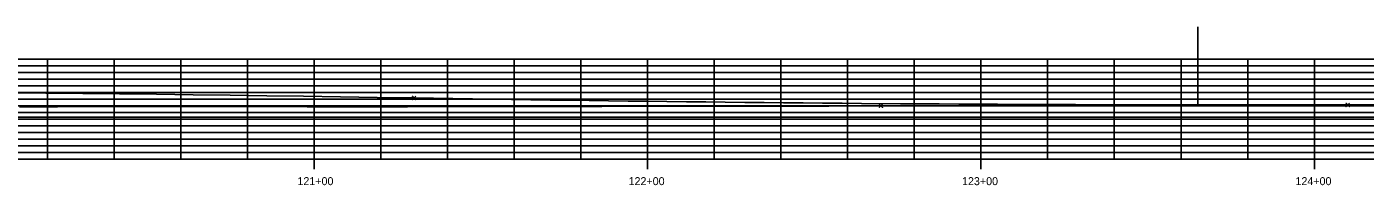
# Model space of a CAD drawing. Extents: x 1676565 to 1681112, y 227357 to 229815.
# Drawn here: x 1680181.1 to 1680582.6, y 229581 to 229628.6 of the extents above; entities that cross this region are included whole.
import ezdxf

# ---------------------------------------------------------------- set-up
doc = ezdxf.new("R2010")
doc.units = 0
for name, color, linetype in [('Default', 7, 'Continuous'), ('R_Axis', 7, 'Continuous'), ('R_Axis Annot', 7, 'Continuous'), ('R_Exist Surface', 7, 'Continuous'), ('R_Grid', 7, 'Continuous'), ('R_No Plot', 7, 'Continuous'), ('R_Point Sym', 7, 'Continuous'), ('R_Water', 7, 'Continuous')]:
    doc.layers.add(name, color=color, linetype=linetype)

msp = doc.modelspace()

# ---------------------------------------------------------------- linework, layer by layer
at = {"layer": 'Default'}
for points in [[(1680175.85, 229608.79), (1680186.89, 229608.68), (1680197.93, 229608.56), (1680208.97, 229608.44), (1680220.02, 229608.31), (1680231.06, 229608.17), (1680242.1, 229608.03), (1680253.14, 229607.88), (1680264.18, 229607.72), (1680275.22, 229607.56), (1680286.27, 229607.39), (1680297.31, 229607.21)], [(1680297.31, 229607.21), (1680303.14, 229607.11), (1680308.97, 229607.02), (1680314.81, 229606.93), (1680320.64, 229606.84), (1680326.47, 229606.75), (1680332.31, 229606.67), (1680338.14, 229606.59), (1680343.97, 229606.51), (1680349.81, 229606.43), (1680355.64, 229606.36), (1680361.47, 229606.28), (1680367.31, 229606.21), (1680373.14, 229606.14), (1680378.97, 229606.08), (1680384.81, 229606.01), (1680390.64, 229605.95), (1680396.47, 229605.89), (1680402.31, 229605.83), (1680408.14, 229605.78), (1680413.97, 229605.73), (1680419.81, 229605.68), (1680425.64, 229605.63), (1680431.47, 229605.58), (1680443.14, 229605.5), (1680448.97, 229605.46), (1680454.81, 229605.42), (1680460.64, 229605.38), (1680466.47, 229605.35), (1680472.31, 229605.32), (1680478.14, 229605.29), (1680483.97, 229605.27), (1680489.81, 229605.24), (1680495.64, 229605.22), (1680501.47, 229605.2), (1680507.31, 229605.18), (1680513.14, 229605.17), (1680518.97, 229605.15), (1680524.81, 229605.14), (1680530.64, 229605.14), (1680536.47, 229605.13), (1680542.31, 229605.13), (1680548.14, 229605.12), (1680553.97, 229605.12), (1680559.81, 229605.13), (1680565.64, 229605.13), (1680571.47, 229605.14), (1680577.31, 229605.15)]]:
    msp.add_lwpolyline(points, dxfattribs=at)
at = {"layer": 'R_Axis'}
msp.add_line((1678167.31, 229588.83), (1681067.31, 229588.83), dxfattribs=at)
at = {"layer": 'R_Exist Surface'}
msp.add_lwpolyline([(1680178.98, 229604.58), (1680190.32, 229604.59), (1680203.93, 229604.61), (1680204.12, 229604.61), (1680204.84, 229604.61), (1680227.46, 229604.63), (1680228.89, 229604.63), (1680229.3, 229604.63), (1680250.08, 229604.61), (1680250.24, 229604.61), (1680265.2, 229604.6), (1680271.59, 229604.59), (1680272.71, 229604.59), (1680277.09, 229604.59), (1680290.61, 229604.6), (1680290.79, 229604.6), (1680290.97, 229604.6), (1680295.33, 229604.6), (1680309.99, 229604.61), (1680310.28, 229604.61), (1680317.96, 229604.63), (1680324.46, 229604.64), (1680324.72, 229604.64), (1680338.94, 229604.67), (1680339.15, 229604.67), (1680353.42, 229604.7), (1680353.59, 229604.7), (1680367.9, 229604.72), (1680368.01, 229604.72), (1680381.34, 229604.73), (1680381.42, 229604.74), (1680394.79, 229604.75), (1680394.83, 229604.75), (1680408.23, 229604.76), (1680408.24, 229604.76), (1680413.34, 229604.76), (1680421.65, 229604.77), (1680421.67, 229604.77), (1680434.92, 229604.81), (1680434.93, 229604.81), (1680448.18, 229604.86), (1680461.43, 229604.91), (1680474.67, 229604.95), (1680474.69, 229604.95), (1680474.72, 229604.95), (1680495.86, 229604.97), (1680496.13, 229604.97), (1680511.62, 229605.01), (1680511.74, 229605.01), (1680525.33, 229605.04), (1680527.35, 229605.05), (1680527.37, 229605.05), (1680540.79, 229605.08), (1680540.88, 229605.08), (1680554.22, 229605.1), (1680554.38, 229605.1), (1680554.54, 229605.1), (1680567.88, 229605.13), (1680568.11, 229605.13), (1680581.37, 229605.16), (1680581.73, 229605.16), (1680596.3, 229605.16)], dxfattribs=at)
at = {"layer": 'R_Grid'}
for p, q in [((1678167.31, 229618.83), (1681067.31, 229618.83)), ((1678167.31, 229618.83), (1681067.31, 229618.83)), ((1678167.31, 229616.83), (1681067.31, 229616.83)), ((1680187.31, 229588.83), (1680187.31, 229618.83)), ((1680207.31, 229588.83), (1680207.31, 229618.83)), ((1680227.31, 229588.83), (1680227.31, 229618.83)), ((1680247.31, 229588.83), (1680247.31, 229618.83)), ((1680267.31, 229588.83), (1680267.31, 229618.83)), ((1680287.31, 229588.83), (1680287.31, 229618.83)), ((1680307.31, 229588.83), (1680307.31, 229618.83)), ((1680327.31, 229588.83), (1680327.31, 229618.83)), ((1680347.31, 229588.83), (1680347.31, 229618.83)), ((1680367.31, 229588.83), (1680367.31, 229618.83)), ((1680387.31, 229588.83), (1680387.31, 229618.83)), ((1680407.31, 229588.83), (1680407.31, 229618.83)), ((1680427.31, 229588.83), (1680427.31, 229618.83)), ((1680447.31, 229588.83), (1680447.31, 229618.83)), ((1680467.31, 229588.83), (1680467.31, 229618.83)), ((1680487.31, 229588.83), (1680487.31, 229618.83)), ((1680507.31, 229588.83), (1680507.31, 229618.83)), ((1680527.31, 229588.83), (1680527.31, 229618.83)), ((1680547.31, 229588.83), (1680547.31, 229618.83)), ((1680567.31, 229588.83), (1680567.31, 229618.83)), ((1678167.31, 229614.83), (1681067.31, 229614.83)), ((1678167.31, 229612.83), (1681067.31, 229612.83)), ((1678167.31, 229610.83), (1681067.31, 229610.83)), ((1678167.31, 229608.83), (1681067.31, 229608.83)), ((1678167.31, 229606.83), (1681067.31, 229606.83)), ((1678167.31, 229604.83), (1681067.31, 229604.83)), ((1678167.31, 229602.83), (1681067.31, 229602.83)), ((1678167.31, 229600.83), (1681067.31, 229600.83)), ((1678167.31, 229598.83), (1681067.31, 229598.83)), ((1678167.31, 229596.83), (1681067.31, 229596.83)), ((1678167.31, 229594.83), (1681067.31, 229594.83)), ((1678167.31, 229592.83), (1681067.31, 229592.83)), ((1678167.31, 229590.83), (1681067.31, 229590.83)), ((1680267.31, 229585.83), (1680267.31, 229588.83)), ((1680367.31, 229585.83), (1680367.31, 229588.83)), ((1680467.31, 229585.83), (1680467.31, 229588.83)), ((1680567.31, 229585.83), (1680567.31, 229588.83))]:
    msp.add_line(p, q, dxfattribs=at)
at = {"layer": 'R_No Plot'}
msp.add_line((1680532.31, 229605.22), (1680532.31, 229628.62), dxfattribs=at)
at = {"layer": 'R_Point Sym'}
for points in [[(1680297.31, 229607.21), (1680296.81, 229607.71), (1680297.31, 229607.21), (1680296.81, 229606.71), (1680297.31, 229607.21), (1680297.81, 229606.71), (1680297.31, 229607.21), (1680297.81, 229607.71)], [(1680437.31, 229604.9), (1680436.81, 229605.4), (1680437.31, 229604.9), (1680436.81, 229604.4), (1680437.31, 229604.9), (1680437.81, 229604.4), (1680437.31, 229604.9), (1680437.81, 229605.4)], [(1680577.31, 229605.15), (1680576.81, 229605.65), (1680577.31, 229605.15), (1680576.81, 229604.65), (1680577.31, 229605.15), (1680577.81, 229604.65), (1680577.31, 229605.15), (1680577.81, 229605.65)]]:
    msp.add_lwpolyline(points, dxfattribs=at)
at = {"layer": 'R_Water'}
msp.add_line((1681080.69, 229601.46), (1678154.35, 229601.46), dxfattribs=at)

# ---------------------------------------------------------------- texts
at = {"layer": 'R_Axis Annot'}
for s, p in [('121+00', (1680262.31, 229581.03)), ('122+00', (1680361.63, 229581.03)), ('123+00', (1680461.63, 229581.03)), ('124+00', (1680561.63, 229581.03))]:
    msp.add_text(s, height=2.4, dxfattribs=at).set_placement(p)

doc.saveas('drawing.dxf')
